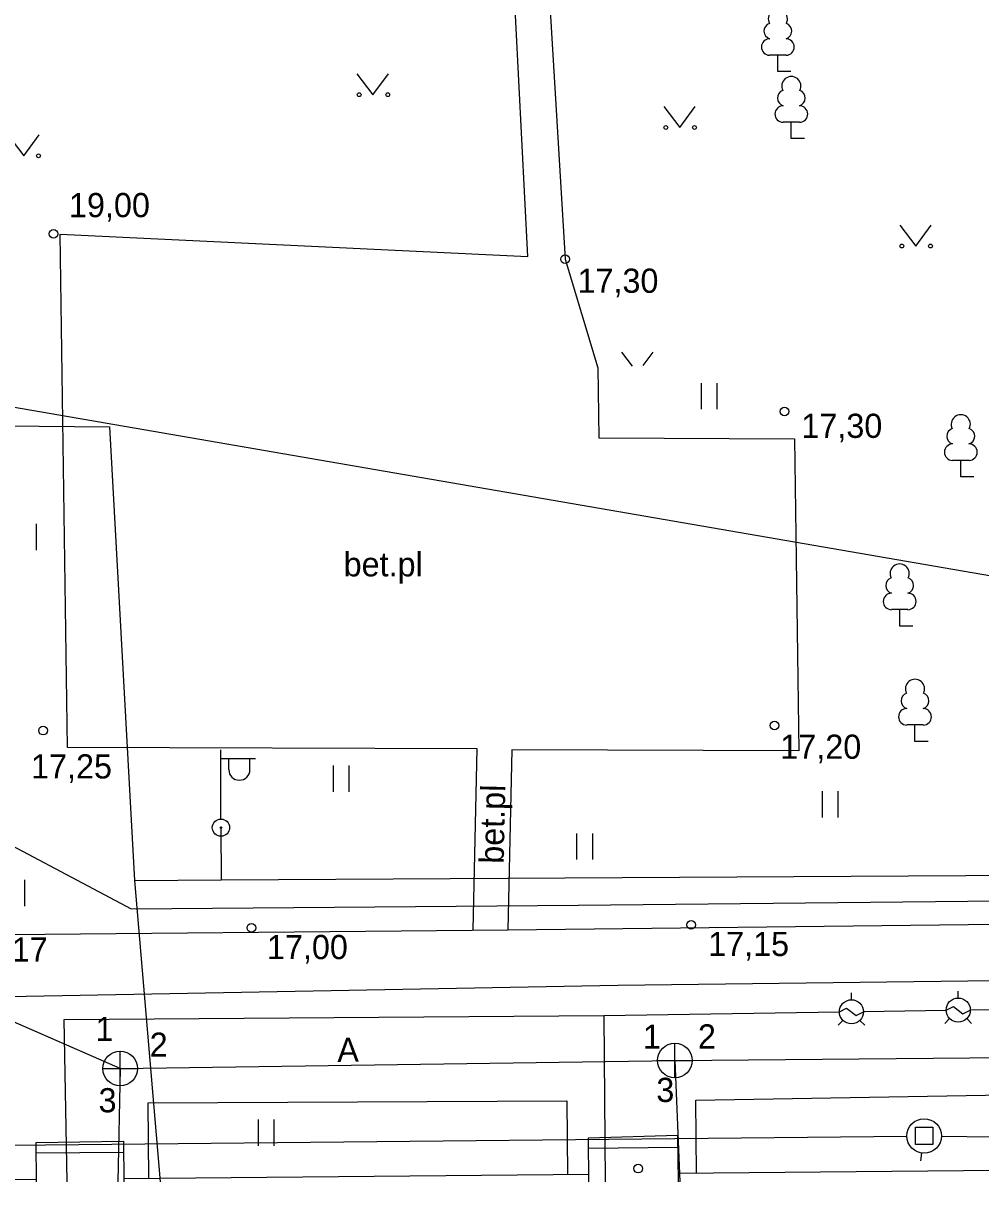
# Model space of a CAD drawing. Extents: x 713540 to 713867, y 6589774 to 6590061.
# Drawn here: x 713739.67 to 713767.39, y 6589774.07 to 6589807.61 of the extents above; entities that cross this region are included whole.
import ezdxf

# ---------------------------------------------------------------- set-up
doc = ezdxf.new("R2010")
doc.units = 0
for name, color, linetype in [('DKAEV', 7, 'Continuous'), ('HALJASTUS', 7, 'Continuous'), ('HOONE', 7, 'Continuous'), ('HOONEDET', 7, 'Continuous'), ('KKAEV', 7, 'Continuous'), ('KORGUS', 7, 'Continuous'), ('KTRASS', 7, 'Continuous'), ('MPKAABEL', 7, 'Continuous'), ('POST', 7, 'Continuous'), ('PUU', 7, 'Continuous'), ('SITRASS', 7, 'Continuous'), ('TEE', 7, 'Continuous'), ('TORU NR', 7, 'Continuous'), ('По умолчанию', 7, 'Continuous')]:
    doc.layers.add(name, color=color, linetype=linetype)

msp = doc.modelspace()

# ---------------------------------------------------------------- linework, layer by layer
at = {"layer": 'DKAEV'}
for p, q in [((713765.494, 6589775.146), (713765.494, 6589775.646)), ((713765.494, 6589775.646), (713765.994, 6589775.646)), ((713765.994, 6589775.646), (713765.994, 6589775.146)), ((713765.994, 6589775.146), (713765.494, 6589775.146))]:
    msp.add_line(p, q, dxfattribs=at)
msp.add_circle((713765.744, 6589775.396), 0.5, dxfattribs=at)
at = {"layer": 'HALJASTUS'}
for p, q in [((713749.327, 6589806.147), (713749.79, 6589805.54)), ((713749.79, 6589805.54), (713750.236, 6589806.147)), ((713758.207, 6589805.197), (713758.67, 6589804.59)), ((713758.67, 6589804.59), (713759.116, 6589805.197)), ((713739.217, 6589804.377), (713739.68, 6589803.77)), ((713739.68, 6589803.77), (713740.126, 6589804.377)), ((713765.037, 6589801.767), (713765.5, 6589801.16)), ((713765.5, 6589801.16), (713765.946, 6589801.767)), ((713759.29, 6589797.194), (713759.29, 6589796.433)), ((713759.745, 6589797.194), (713759.745, 6589796.433)), ((713740.04, 6589793.113), (713740.04, 6589792.352)), ((713748.635, 6589786.121), (713748.635, 6589785.36)), ((713749.09, 6589786.121), (713749.09, 6589785.36)), ((713762.79, 6589785.376), (713762.79, 6589784.615)), ((713763.245, 6589785.376), (713763.245, 6589784.615)), ((713755.685, 6589784.157), (713755.685, 6589783.396)), ((713756.14, 6589784.157), (713756.14, 6589783.396)), ((713739.708, 6589782.808), (713739.708, 6589782.047)), ((713746.466, 6589775.871), (713746.466, 6589775.11)), ((713746.921, 6589775.871), (713746.921, 6589775.11))]:
    msp.add_line(p, q, dxfattribs=at)
for centre in [(713749.389, 6589805.54), (713750.218, 6589805.54), (713758.269, 6589804.59), (713759.098, 6589804.59), (713740.108, 6589803.77), (713765.099, 6589801.16), (713765.928, 6589801.16)]:
    msp.add_circle(centre, 0.055, dxfattribs=at)
at = {"layer": 'HOONE'}
for p, q in [((713763.64, 6589779.34), (713763.64, 6589779.537)), ((713766.73, 6589779.39), (713766.73, 6589779.587)), ((713763.29, 6589778.988), (713763.501, 6589779.094)), ((713763.501, 6589779.094), (713763.779, 6589778.886)), ((713766.38, 6589779.038), (713766.591, 6589779.144)), ((713766.591, 6589779.144), (713766.869, 6589778.936)), ((713763.393, 6589778.743), (713763.253, 6589778.603)), ((713763.779, 6589778.886), (713763.99, 6589778.992)), ((713763.887, 6589778.743), (713764.027, 6589778.603)), ((713766.483, 6589778.793), (713766.343, 6589778.653)), ((713766.869, 6589778.936), (713767.08, 6589779.042)), ((713766.977, 6589778.793), (713767.117, 6589778.653))]:
    msp.add_line(p, q, dxfattribs=at)
for points in [[(713704.798, 6589774.068), (713704.5, 6589777.88), (713726.25, 6589779.19), (713756.88, 6589779.76), (713802.063, 6589780.323), (713802.696, 6589780.331), (713812.22, 6589780.45), (713824.89, 6589807.23), (713827.83, 6589806.02)], [(713724.813, 6589799.015), (713793.791, 6589787.108)], [(713767.08, 6589779.045), (713772.63, 6589779.13), (713788.09, 6589779.34)], [(713740.939, 6589774.068), (713740.85, 6589778.77), (713756.47, 6589778.88), (713763.29, 6589778.985)], [(713756.47, 6589778.88), (713756.515, 6589774.068)], [(713763.99, 6589778.996), (713766.38, 6589779.034)], [(713734.548, 6589775.083), (713765.244, 6589775.391)], [(713756.038, 6589774.068), (713756.026, 6589775.345), (713758.607, 6589775.42), (713758.62, 6589774.068)], [(713766.244, 6589775.389), (713798.391, 6589774.964)], [(713740.053, 6589774.068), (713740.042, 6589775.208), (713742.565, 6589775.242), (713742.576, 6589774.068)], [(713765.65, 6589774.673), (713765.679, 6589774.9)]]:
    msp.add_lwpolyline(points, dxfattribs=at)
for centre in [(713763.64, 6589778.99), (713766.73, 6589779.04)]:
    msp.add_circle(centre, 0.35, dxfattribs=at)
at = {"layer": 'HOONEDET'}
for p, q in [((713756.029, 6589775.045), (713758.611, 6589775.069)), ((713740.045, 6589774.908), (713742.568, 6589774.931))]:
    msp.add_line(p, q, dxfattribs=at)
at = {"layer": 'KKAEV'}
for p, q in [((713758.53, 6589777.081), (713758.53, 6589778.081)), ((713742.473, 6589776.848), (713742.473, 6589777.848)), ((713758.03, 6589777.581), (713759.03, 6589777.581)), ((713741.973, 6589777.348), (713742.973, 6589777.348))]:
    msp.add_line(p, q, dxfattribs=at)
for centre in [(713758.53, 6589777.581), (713742.473, 6589777.348)]:
    msp.add_circle(centre, 0.5, dxfattribs=at)
at = {"layer": 'KORGUS'}
for centre in [(713740.54, 6589801.51), (713755.35, 6589800.78), (713761.7, 6589796.37), (713740.24, 6589787.13), (713761.41, 6589787.28), (713746.27, 6589781.42), (713759, 6589781.51), (713757.47, 6589774.45)]:
    msp.add_circle(centre, 0.125, dxfattribs=at)
at = {"layer": 'KTRASS'}
for p, q in [((713742.473, 6589777.348), (713730.949, 6589782.394)), ((713758.53, 6589777.581), (713774.932, 6589777.721)), ((713742.473, 6589777.348), (713758.53, 6589777.581)), ((713758.53, 6589777.581), (713758.669, 6589774.068)), ((713742.473, 6589777.348), (713742.403, 6589774.068))]:
    msp.add_line(p, q, dxfattribs=at)
at = {"layer": 'MPKAABEL'}
for points in [[(713733.277, 6589792.111), (713733.27, 6589793.4), (713736.06, 6589795.98), (713742.16, 6589795.93), (713742.89, 6589782.79), (713745.398, 6589782.812), (713776.9, 6589782.991), (713793.62, 6589783.07), (713794.36, 6589783.55), (713803.66, 6589789.6), (713809, 6589792.98)], [(713745.39, 6589784.322), (713745.398, 6589782.812)], [(713742.89, 6589782.79), (713743.635, 6589774.068)]]:
    msp.add_lwpolyline(points, dxfattribs=at)
at = {"layer": 'POST'}
for p, q in [((713745.39, 6589784.572), (713745.39, 6589786.572)), ((713745.39, 6589786.322), (713746.39, 6589786.322)), ((713745.616, 6589786.001), (713745.616, 6589786.322)), ((713746.229, 6589786.001), (713746.229, 6589786.322))]:
    msp.add_line(p, q, dxfattribs=at)
for radius in [0.25, 0.0234]:
    msp.add_circle((713745.39, 6589784.322), radius, dxfattribs=at)
msp.add_arc((713745.923, 6589786.001), 0.306, 180, 0, dxfattribs=at)
at = {"layer": 'PUU'}
for p, q in [((713761.75, 6589806.685), (713761.27, 6589806.685)), ((713761.51, 6589806.21), (713761.51, 6589806.685)), ((713761.89, 6589806.21), (713761.51, 6589806.21)), ((713762.14, 6589804.745), (713761.66, 6589804.745)), ((713761.9, 6589804.27), (713761.9, 6589804.745)), ((713762.28, 6589804.27), (713761.9, 6589804.27)), ((713767.045, 6589794.954), (713766.565, 6589794.954)), ((713766.805, 6589794.479), (713766.805, 6589794.954)), ((713767.185, 6589794.479), (713766.805, 6589794.479)), ((713765.276, 6589790.633), (713764.796, 6589790.633)), ((713765.036, 6589790.158), (713765.036, 6589790.633)), ((713765.416, 6589790.158), (713765.036, 6589790.158)), ((713765.719, 6589787.294), (713765.239, 6589787.294)), ((713765.479, 6589786.819), (713765.479, 6589787.294)), ((713765.859, 6589786.819), (713765.479, 6589786.819))]:
    msp.add_line(p, q, dxfattribs=at)
for centre, radius, start, end in [((713761.51, 6589807.73), 0.277, 332.5799, 207.4201), ((713761.34, 6589807.383), 0.233, 109.0217, 253.1415), ((713761.68, 6589807.383), 0.233, 286.8508, 70.9859), ((713761.273, 6589806.922), 0.238, 90.0016, 269.3953), ((713761.747, 6589806.922), 0.238, 270.6047, 89.9984), ((713761.9, 6589805.79), 0.277, 332.5799, 207.4201), ((713761.73, 6589805.443), 0.233, 109.0217, 253.1415), ((713762.07, 6589805.443), 0.233, 286.8508, 70.9859), ((713761.663, 6589804.982), 0.238, 90.0016, 269.3953), ((713762.137, 6589804.982), 0.238, 270.6047, 89.9984), ((713766.805, 6589795.999), 0.277, 332.5799, 207.4201), ((713766.635, 6589795.652), 0.233, 109.0217, 253.1415), ((713766.975, 6589795.652), 0.233, 286.8508, 70.9859), ((713766.568, 6589795.191), 0.238, 90.0016, 269.3953), ((713767.043, 6589795.191), 0.238, 270.6047, 89.9984), ((713765.036, 6589791.678), 0.277, 332.5799, 207.4201), ((713764.866, 6589791.33), 0.233, 109.0217, 253.1415), ((713765.206, 6589791.33), 0.233, 286.8508, 70.9859), ((713764.799, 6589790.87), 0.238, 90.0016, 269.3953), ((713765.274, 6589790.87), 0.238, 270.6047, 89.9984), ((713765.479, 6589788.339), 0.277, 332.5799, 207.4201), ((713765.309, 6589787.991), 0.233, 109.0217, 253.1415), ((713765.649, 6589787.991), 0.233, 286.8508, 70.9859), ((713765.241, 6589787.531), 0.238, 90.0016, 269.3953), ((713765.716, 6589787.531), 0.238, 270.6047, 89.9984)]:
    msp.add_arc(centre, radius, start, end, dxfattribs=at)
at = {"layer": 'SITRASS'}
msp.add_lwpolyline([(713726.305, 6589783.201), (713726.59, 6589783.58), (713728.41, 6589783.99), (713737.91, 6589784.56), (713742.79, 6589781.97), (713755.73, 6589782.08), (713785.81, 6589782.39), (713794.06, 6589782.35), (713801.725, 6589787.367), (713802.954, 6589788.171), (713811.95, 6589794.06), (713820.13, 6589802.81), (713825.16, 6589813.2), (713832.56, 6589810.04)], dxfattribs=at)
at = {"layer": 'TEE'}
for points in [[(713752.692, 6589781.359), (713752.81, 6589786.603), (713740.952, 6589786.641), (713740.736, 6589801.501), (713754.27, 6589800.86), (713753.4, 6589817.85), (713753.33, 6589821.92)], [(713754.2, 6589821.96), (713754.35, 6589817.42), (713755.35, 6589800.78), (713756.302, 6589797.631), (713756.332, 6589795.608), (713761.988, 6589795.576), (713762.12, 6589786.544), (713753.809, 6589786.575), (713753.691, 6589781.368)], [(713737.195, 6589781.213), (713753.691, 6589781.368), (713775.346, 6589781.61), (713788.698, 6589781.868), (713801.96, 6589782.454)], [(713743.304, 6589774.162), (713743.284, 6589776.355), (713755.403, 6589776.416), (713755.423, 6589774.275)], [(713759.151, 6589774.31), (713759.132, 6589776.432), (713771.432, 6589776.643), (713771.453, 6589774.425)], [(713772.043, 6589774.431), (713758.618, 6589774.305)], [(713740.053, 6589774.131), (713733.312, 6589774.068)], [(713756.036, 6589774.281), (713742.575, 6589774.155)]]:
    msp.add_lwpolyline(points, dxfattribs=at)
at = {"layer": 'По умолчанию'}
for p, q in [((713756.987, 6589798.087), (713757.294, 6589797.684)), ((713757.613, 6589797.702), (713757.896, 6589798.087))]:
    msp.add_line(p, q, dxfattribs=at)

# ---------------------------------------------------------------- texts
at = {"layer": 'HOONEDET'}
msp.add_text('bet.pl', height=0.7, dxfattribs=at).set_placement((713748.941, 6589791.596))
msp.add_text('bet.pl', height=0.7, rotation=88.7127, dxfattribs=at).set_placement((713753.572, 6589783.271))
at = {"layer": 'KORGUS'}
for s, p in [('19,00', (713740.991, 6589801.995)), ('17,30', (713755.711, 6589799.805)), ('17,30', (713762.191, 6589795.605)), ('17,20', (713761.581, 6589786.315)), ('17,25', (713739.893, 6589785.745)), ('17,17', (713738.033, 6589780.445)), ('17,00', (713746.721, 6589780.515)), ('17,15', (713759.493, 6589780.605))]:
    msp.add_text(s, height=0.7, dxfattribs=at).set_placement(p)
at = {"layer": 'TEE'}
msp.add_text('A', height=0.7, rotation=0.5403, dxfattribs=at).set_placement((713748.76, 6589777.538))
at = {"layer": 'TORU NR'}
for s, p in [('1', (713741.756, 6589778.143)), ('2', (713743.326, 6589777.688)), ('1', (713757.605, 6589777.922)), ('2', (713759.196, 6589777.928)), ('3', (713757.992, 6589776.38)), ('3', (713741.847, 6589776.08))]:
    msp.add_text(s, height=0.7, dxfattribs=at).set_placement(p)

doc.saveas('drawing.dxf')
